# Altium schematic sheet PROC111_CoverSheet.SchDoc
size 431 x 279 mm; Date: Not shown in title block; ApprovedBy: Not shown in title block; CheckedBy: Not shown in title block; Author: Not shown in title block; CompanyName: Not shown in title block; Engineer: Not shown in title block; Organization: Not shown in title block; Address1: Not shown in title block; Address2: Not shown in title block; Address3: Not shown in title block; Address4: Not shown in title block; DocumentNumber: 1; Revision: Use project parameter SCH_Rev; SheetNumber: 1; SheetTotal: 24; PageSetup: Record=PageOptions¦CenterHorizontal=True¦CenterVertical=True¦PrintScale=1.00¦XCorrection=1.00¦YCorrection=1.00¦PrintKind=0¦BorderSize=5000000¦LeftOffset=0¦BottomOffset=0¦Orientation=2¦PaperLength=1000¦PaperWidth=1000¦Scale=100¦PaperSource=15¦PrintQuality=600¦MediaType=1¦DitherType=10¦PaperKind=Letter¦PrintScaleMode=1
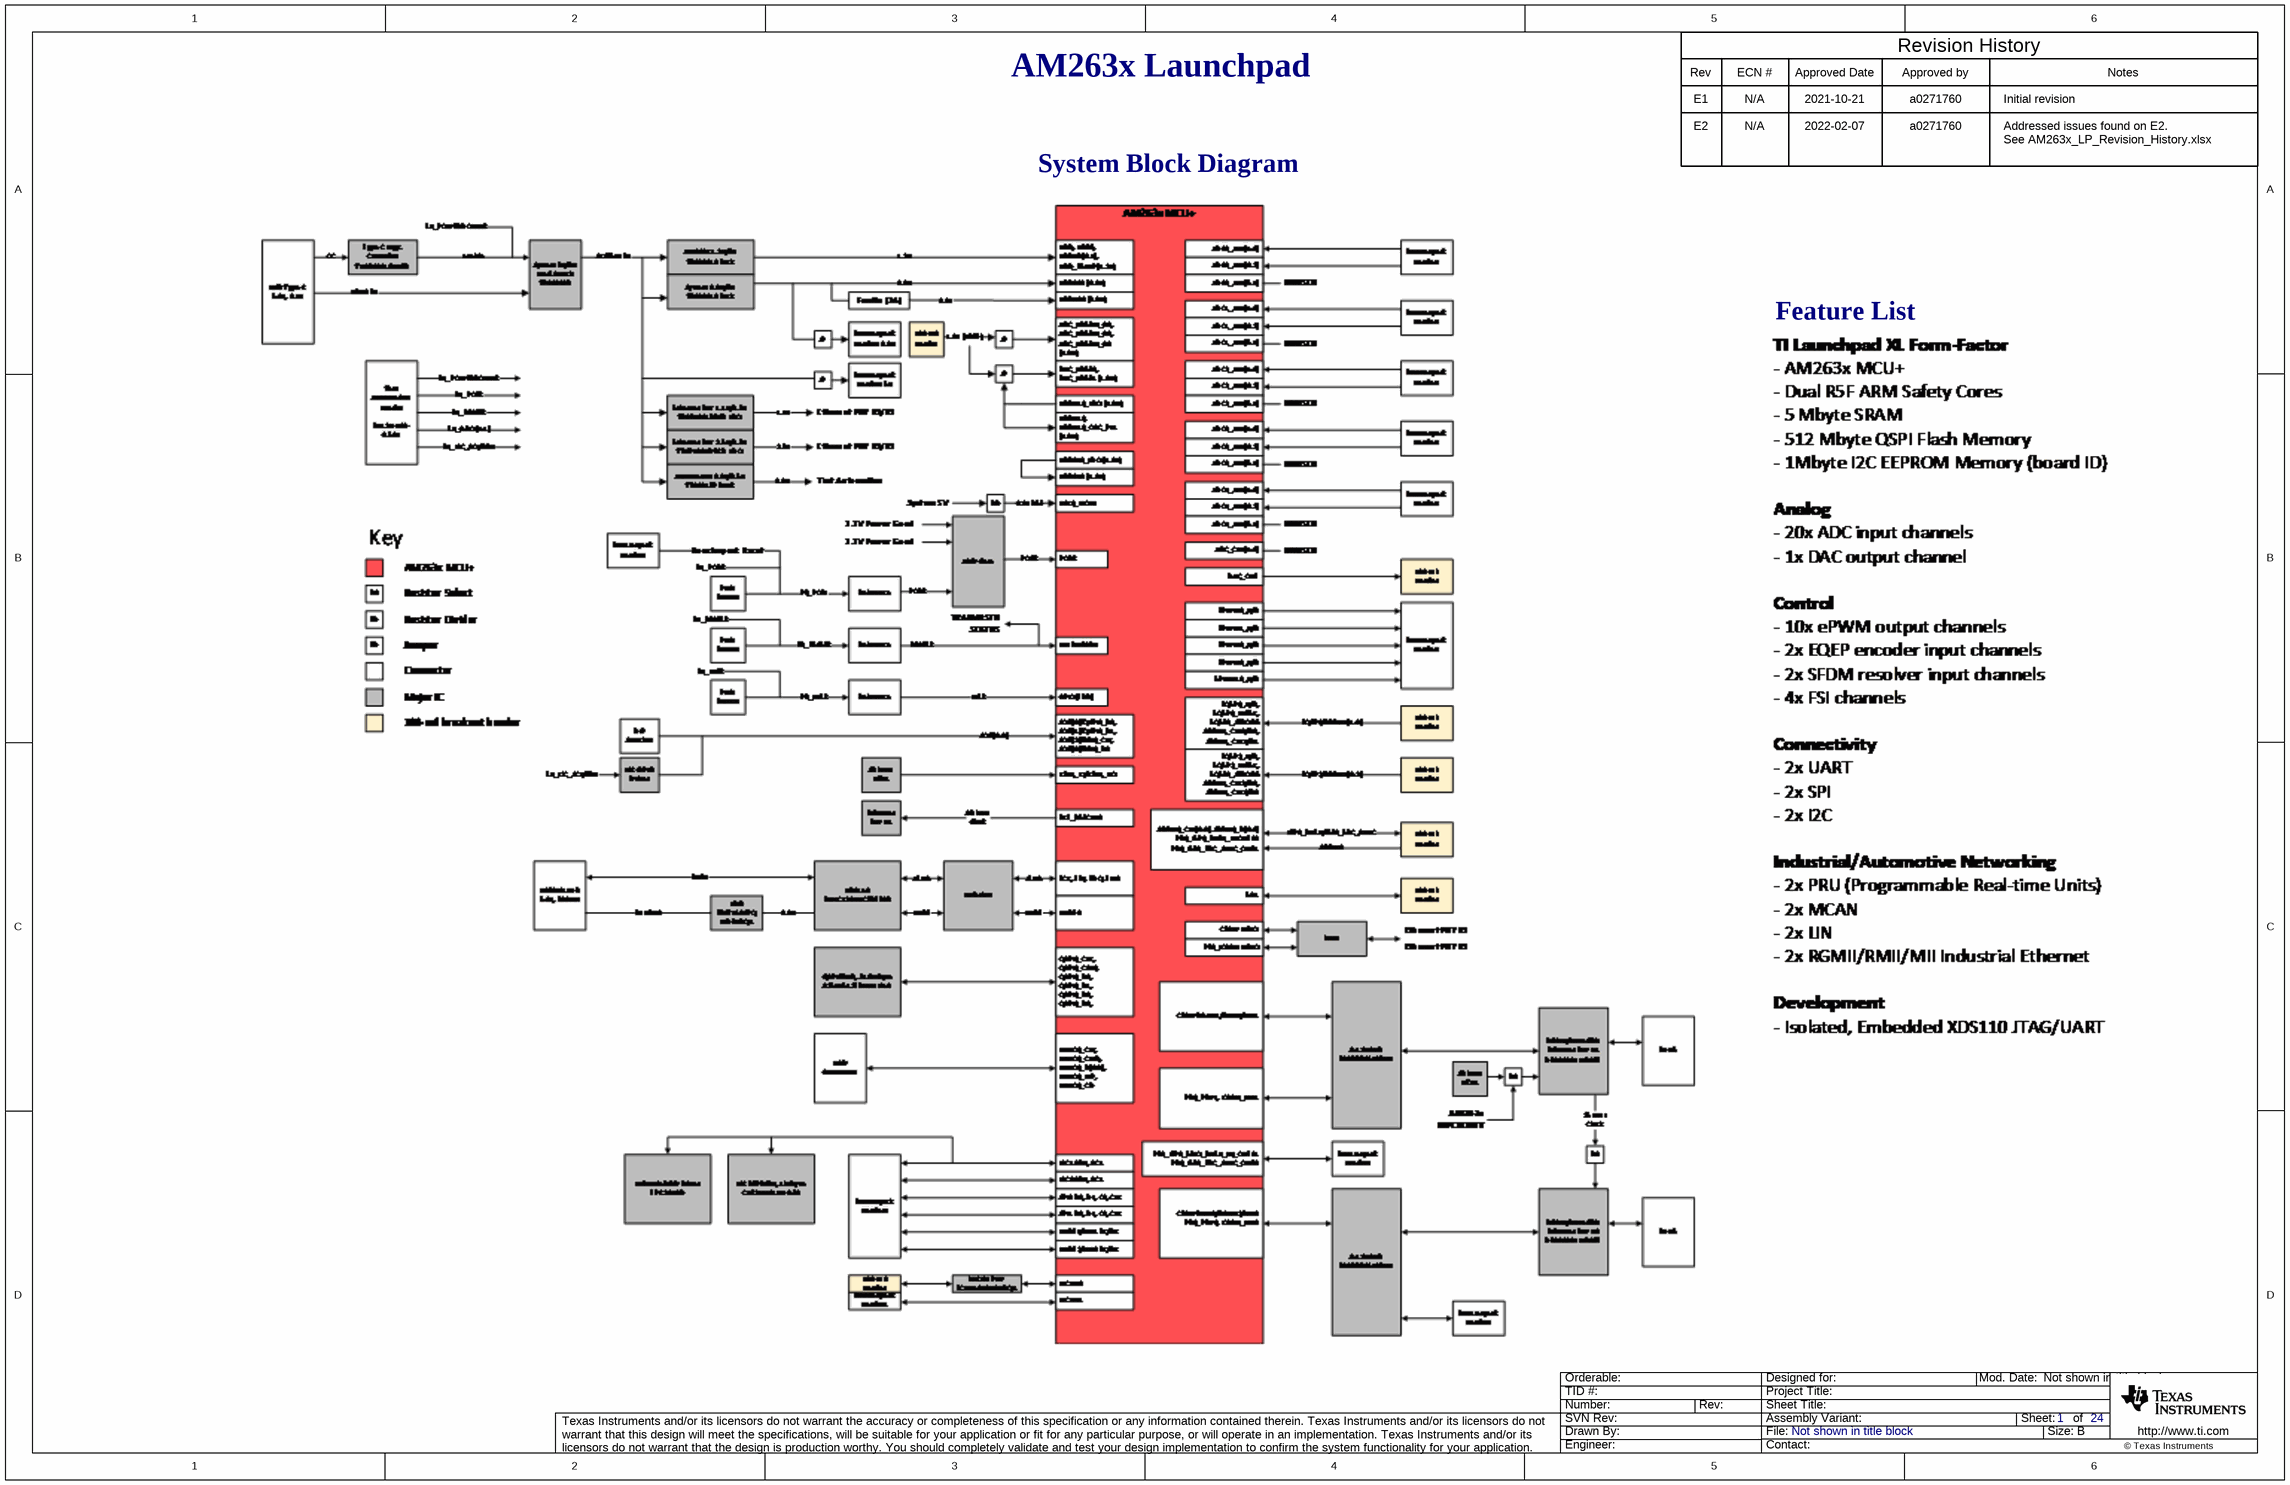
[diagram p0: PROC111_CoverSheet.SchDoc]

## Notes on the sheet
- AM263x Launchpad
- Rev
- E1
- ECN #
- N/A
- Approved Date
- 2021-10-21
- Approved by
- a0271760
- Revision History
- Initial revision
- Notes
- E2
- 2022-02-07
- Addressed issues found on E2.
- See AM263x_LP_Revision_History.xlsx
- System Block Diagram
- Feature List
